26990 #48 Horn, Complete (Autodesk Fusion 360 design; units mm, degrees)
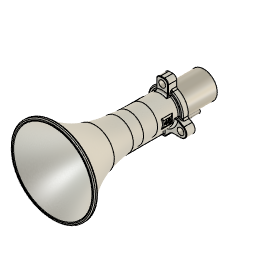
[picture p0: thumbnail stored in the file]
parameter "Bolt_Hole_Tolerance" = 1.5875 (= "( 1 / 16 ) * 1 in")
parameter "Dowel_Hole_Tolerance" = 0.0248 (= "( 1 / 1024 ) * 1 in")
canvas "Canvas1"
canvas "Canvas10"
sketch "Main Profile" plane through (0, 0, 0) normal (1, 0, 0) x axis (0, 1, 0)
  line L1 (0, -22.225) -> (0, 22.225)
  line L2 (-53.975, 22.225) -> (0, 22.225)
  line L3 (-53.975, 44.45) -> (-53.975, 22.225)
  line L4 (-248.4438, 0) -> (0, 0)
  line L5 (-68.2625, 44.45) -> (-53.975, 44.45)
  line L6 (-53.975, -22.225) -> (0, -22.225)
  line L7 (-53.975, 22.225) -> (-53.975, -22.225)
  line L8 (-53.975, -38.1) -> (-53.975, -22.225)
  line L9 (-68.2625, -38.1) -> (-53.975, -38.1)
  line L10 (-68.2625, 44.45) -> (-68.2625, -38.1)
  line L11 (-141.1977, 22.225) -> (0, 11.1125)
  line L12 (-63.5, 28.575) -> (-53.975, 28.575)
  line L13 (-63.5, 19.2949) -> (-63.5, 28.575)
  line L14 (-140.9486, 25.3902) -> (-63.5, 19.2949)
  line L15 (-248.4438, -69.0563) -> (-248.4437, 69.0562)
  line L16 (-68.2625, 19.6697) -> (-68.2625, 44.45)
  line L17 (9.1828, 34.925) -> (-68.2625, 34.925)
  line L18 (-34.1313, 22.225) -> (-34.1313, -22.225)
  line L19 (-68.2625, -18.1085) -> (-68.2625, -38.1)
  line L20 (-243.6812, 69.0562) -> (-248.4437, 69.0562)
  line L21 (-243.6813, 65.2268) -> (-243.6812, 69.0562)
  line L22 (-187.3946, -34.925) -> (-68.2625, -34.925)
  line L23 (-98.8407, 23.0188) -> (-68.2625, 23.0187)
  line L24 (-141.1977, 0) -> (-141.1977, 22.225)
  line L25 (-141.1977, -22.225) -> (0, -11.1125)
  line L26 (-243.6813, -65.2268) -> (-243.6812, -69.0563)
  line L27 (-243.6812, -69.0563) -> (-248.4437, -69.0563)
  line L28 (-98.8407, -23.0188) -> (-68.2625, -23.0188)
  line L29 (-140.9486, -25.3902) -> (-63.5, -19.2949)
  line L30 (-63.5, 23.0187) -> (-68.2625, 23.0187)
  arc A1 centre (-125.9018, 216.5783) radius 194.9543 clockwise from (-141.1977, 22.225) to (-248.4437, 64.9517)
  arc A2 centre (-125.9018, 216.5783) radius 191.7793 clockwise from (-140.9486, 25.3902) to (-248.4437, 69.0562)
  arc A3 centre (-125.9018, -216.5783) radius 194.9543 clockwise from (-248.4437, -64.9517) to (-141.1977, -22.225)
  arc A4 centre (-125.9018, -216.5783) radius 191.7793 clockwise from (-248.4437, -69.0563) to (-140.9486, -25.3902)
  arc A5 centre (-98.8407, 327.8188) radius 304.8 clockwise from (-98.8407, 23.0188) to (-122.755, 23.9583)
  arc A6 centre (-98.8407, -327.8188) radius 304.8 clockwise from (-122.755, -23.9583) to (-98.8407, -23.0188)
  point P4 (0, 0)
  point P1 (0, 0)
  point P7 (0, 0)
  point P13 (0, 11.1125)
  point P15 (-53.975, 28.575)
  point P21 (-248.4438, 0)
  point P8 (-248.4438, 0)
  point P22 (-68.2625, 19.6697)
  point P23 (-68.2625, 34.925)
  point P25 (-34.1313, -22.225)
  point P26 (-34.1313, 22.225)
  point P27 (-68.2625, -18.1085)
  point P30 (-68.2625, -34.925)
  point P32 (-68.2625, 23.0187)
  point P34 (-248.4437, 64.9517)
  point P38 (-141.1977, 0)
  point P36 (-248.4437, 69.0562)
  point P29 (-243.6813, 65.2268)
  point P19 (-248.4437, 69.0562)
  point P39 (0, -11.1125)
  point P14 (-141.1977, 22.225)
  point P40 (-141.1977, -22.225)
  point P17 (-63.5, 19.2949)
  point P51 (-63.5, -19.2949)
  point P18 (-140.9486, 25.3902)
  point P45 (-140.9486, -25.3902)
  point P48 (-248.4437, -69.0563)
  point P28 (-243.6812, 69.0562)
  point P46 (-243.6812, -69.0563)
  point P47 (-243.6813, -65.2268)
  point P49 (-68.2625, -23.0188)
  point P33 (-98.8407, 23.0188)
  point P50 (-98.8407, -23.0188)
  point P42 (-248.4437, -64.9517)
  point P44 (-248.4437, -69.0563)
  point P31 (-187.3946, -34.925)
  point P52 (-63.5, 23.0187)
  point P53 (-122.755, 23.9583)
  point P57 (-98.8407, -23.0188)
  point P56 (-122.755, -23.9583)
  point P2 (0, 22.225)
  point P5 (-53.975, 22.225)
  point P3 (0, -22.225)
  point P6 (-53.975, 44.45)
  point P9 (-68.2625, 44.45)
  point P16 (-63.5, 28.575)
  point P20 (-248.4438, -69.0563)
  point P12 (-68.2625, -38.1)
  vertical L1
  coincident L1 P4
  coincident P1 P4
  midpoint P1 L1
  perpendicular L1 L2
  perpendicular L2 L3
  coincident P1 P7
  perpendicular L1 L4
  perpendicular L3 L5
  perpendicular L1 L6
  vertical L7
  perpendicular L6 L8
  perpendicular L8 L9
  vertical L10
  coincident L1 P13
  coincident L3 P15
  perpendicular L3 L12
  perpendicular L12 L13
  parallel L11 L14
  vertical L15
  midpoint L15 P21
  coincident P8 P21
  coincident L14 P22
  coincident L10 P22
  coincident L10 P23
  perpendicular L16 L17
  coincident L6 P25
  coincident L2 P26
  perpendicular L2 L18
  coincident L10 P27
  perpendicular L9 L19
  perpendicular L15 L20
  vertical L21
  coincident L10 P30
  perpendicular L19 L22
  coincident L10 P32
  horizontal L23
  coincident L15 P34
  tangent L11 A1
  tangent L14 A2
  concentric A1 A2
  coincident L4 P38
  perpendicular L4 L24
  coincident L15 P36
  coincident P29 A2
  coincident P19 P36
  symmetric L4 P13 P39
  symmetric L4 P14 P40
  symmetric L4 P17 P51
  symmetric L4 P18 P45
  symmetric L4 P19 P48
  symmetric L4 P28 P46
  symmetric L4 P29 P47
  symmetric L4 P32 P49
  symmetric L4 P33 P50
  symmetric L4 P34 P42
  symmetric L4 A1 A3
  symmetric L4 P36 P44
  symmetric L4 A2 A4
  coincident P31 A4
  coincident L13 P52
  perpendicular L13 L30
  coincident L14 P53
  tangent L23 A5
  tangent L14 A5
  symmetric L4 P33 P57
  symmetric L4 P53 P56
  symmetric L4 A5 A6
  dimension "d1" distance P2 P5 = 53.975 (= "2 1/8")
  dimension "d2" distance P2 P3 = 44.45 (= "1 3/4")
  dimension "d3" distance P6 L4 = 44.45 (= "1 3/4")
  dimension "d4" distance P6 P9 = 14.2875 (= "( 9 / 16 ) * 1 in")
  dimension "d5" distance L4 L9 = 38.1
  dimension "d6" distance P4 P13 = 11.1125 (= "( 7 / 16 ) * 1 in")
  dimension "d7" distance L11 L14 = 3.175 (= "( 1 / 8 ) * 1 in")
  dimension "d9" distance P15 P16 = 9.525 (= "( 3 / 8 ) * 1 in")
  dimension "d10" distance L4 L12 = 28.575
  dimension "d11" distance L4 L17 = 34.925 (= "1 3/8")
  dimension "d12" distance P19 P20 = 138.1125 (= "5 7/16")
  dimension "d17" distance L1 L18 = 34.1313 (= "1 11/32")
  dimension "d68" distance P19 P28 = 4.7625 (= "( 3 / 16 ) * 1 in")
  dimension "d157" distance L15 L18 = 214.3125 (= "8 7/16")
  dimension "d175" distance P12 P30 = 3.175 (= "( 1 / 8 ) * 1 in")
  dimension "d197" angle L4 L11 = 4.5
  dimension "d198" distance L4 L23 = 23.0187 (= "( 29 / 32 ) * 1 in")
  dimension "d290" distance P14 P38 = 22.225 (= "( 7 / 8 ) * 1 in")
  dimension "d293" radius A5 = 304.8
revolve "Revolve1" sketch "Main Profile" AlongAngle 360
revolve "Revolve3" sketch "Main Profile" AlongAngle 360
fillet "Fillet16" radius 158.75
sketch "Flange Profile" plane through (0, -53.975, 0) normal (0, 1, 0) x axis (-1, 0, 0)
  line L1 (0, 34.925) -> (0, 0)
  line L2 (0, 44.45) -> (0, 34.925)
  line L3 (3.175, 44.45) -> (-3.175, 44.45)
  line L4 (9.525, 31.1085) -> (9.525, 38.1)
  line L5 (-30.2459, -17.4625) -> (0, 0)
  line L6 (30.2459, -17.4625) -> (0, 0)
  line L7 (30.2459, -26.9875) -> (15.0812, -26.9875)
  line L8 (29.9633, -6.3008) -> (35.0084, -9.2136)
  line L9 (0, -31.75) -> (0, 0)
  line L10 (0, -38.1) -> (0, -31.75)
  line L11 (3.9688, -38.1) -> (-3.9688, -38.1)
  line L12 (15.0812, -26.9875) -> (3.9688, -38.1)
  line L13 (-15.0812, -26.9875) -> (-3.9688, -38.1)
  line L14 (-30.2459, -26.9875) -> (-15.0812, -26.9875)
  line L15 (-29.9633, -6.3008) -> (-35.0084, -9.2136)
  line L16 (-9.525, 31.1085) -> (-9.525, 38.1)
  line L17 (9.525, 20.0805) -> (9.525, 31.1085)
  line L18 (-9.525, 20.0805) -> (-9.525, 31.1085)
  line L19 (22.1527, -1.7913) -> (29.9633, -6.3008)
  line L20 (-22.1527, -1.7913) -> (-29.9633, -6.3008)
  circle C1 centre (0, 0) radius 22.225
  circle C2 centre (0, 34.925) radius 5.5563
  arc A1 centre (3.175, 38.1) radius 6.35 clockwise from (3.175, 44.45) to (9.525, 38.1)
  arc A2 centre (15.875, 31.1085) radius 6.35 clockwise from (12.9886, 25.4524) to (9.525, 31.1085)
  arc A3 centre (0, 0) radius 28.575 clockwise from (12.9886, 25.4524) to (28.3957, -3.196)
  circle C3 centre (-30.2459, -17.4625) radius 5.5563
  circle C4 centre (30.2459, -17.4625) radius 5.5563
  arc A4 centre (30.2459, -17.4625) radius 9.525 clockwise from (35.0084, -9.2136) to (30.2459, -26.9875)
  arc A5 centre (31.5508, -3.5512) radius 3.175 clockwise from (29.9633, -6.3008) to (28.3957, -3.196)
  circle C5 centre (0, -31.75) radius 3.9688
  arc A6 centre (-30.2459, -17.4625) radius 9.525 clockwise from (-30.2459, -26.9875) to (-35.0084, -9.2136)
  arc A7 centre (-31.5508, -3.5512) radius 3.175 clockwise from (-28.3957, -3.196) to (-29.9633, -6.3008)
  arc A8 centre (0, 0) radius 28.575 clockwise from (-28.3957, -3.196) to (-12.9886, 25.4524)
  arc A9 centre (-15.875, 31.1085) radius 6.35 clockwise from (-9.525, 31.1085) to (-12.9886, 25.4524)
  arc A10 centre (-3.175, 38.1) radius 6.35 clockwise from (-9.525, 38.1) to (-3.175, 44.45)
  circle C6 centre (0, 0) radius 28.575
  point P1 (0, 0)
  point P3 (0, 0)
  point P4 (0, 34.925)
  point P5 (0, 34.925)
  point P6 (0, 34.925)
  point P10 (0, 44.45)
  point P7 (0, 44.45)
  point P30 (0, 0)
  point P31 (0, -31.75)
  point P32 (0, -31.75)
  point P33 (0, -31.75)
  point P37 (0, -38.1)
  point P34 (0, -38.1)
  point P9 (3.175, 44.45)
  point P52 (-3.175, 44.45)
  point P11 (9.525, 38.1)
  point P50 (-9.525, 38.1)
  point P13 (9.525, 31.1085)
  point P49 (-9.525, 31.1085)
  point P14 (12.9886, 25.4524)
  point P47 (-12.9886, 25.4524)
  point P16 (28.3957, -3.196)
  point P45 (-28.3957, -3.196)
  point P24 (15.0812, -26.9875)
  point P39 (-15.0812, -26.9875)
  point P25 (30.2459, -26.9875)
  point P40 (-30.2459, -26.9875)
  point P26 (35.0084, -9.2136)
  point P42 (-35.0084, -9.2136)
  point P28 (29.9633, -6.3008)
  point P43 (-29.9633, -6.3008)
  point P36 (3.9688, -38.1)
  point P38 (-3.9688, -38.1)
  point P53 (9.525, 20.0805)
  point P54 (-9.525, 20.0805)
  point P55 (22.1527, -1.7913)
  point P56 (-22.1527, -1.7913)
  point P35 (-3.9688, -38.1)
  point P19 (0, 0)
  coincident P1 P3
  vertical L1
  coincident P4 P5
  coincident P5 P6
  parallel L1 L2
  horizontal L3
  coincident L3 P10
  midpoint L3 P10
  coincident P7 P10
  tangent L3 A1
  vertical L4
  tangent A1 L4
  tangent L4 A2
  tangent A2 A3
  concentric C1 A3
  horizontal L7
  tangent L7 A4
  concentric C4 A4
  tangent A4 L8
  tangent L8 A5
  tangent A3 A5
  coincident P1 P30
  vertical L9
  coincident P31 P32
  coincident P32 P33
  parallel L9 L10
  horizontal L11
  midpoint L11 P37
  coincident P34 P37
  symmetric L1 P9 P52
  symmetric L1 P11 P50
  symmetric L1 A1 A10
  symmetric L1 P13 P49
  symmetric L1 P14 P47
  symmetric L1 A2 A9
  symmetric L1 P16 P45
  symmetric L1 A3 A8
  symmetric L1 P24 P39
  symmetric L1 P25 P40
  symmetric L1 P26 P42
  symmetric L1 A4 A6
  symmetric L1 P28 P43
  symmetric L1 A5 A7
  symmetric L1 P36 P38
  coincident C1 P53
  tangent A2 L17
  tangent A9 L18
  coincident C1 P54
  coincident C1 P55
  tangent A5 L19
  coincident C1 P56
  tangent A7 L20
  dimension "d95" distance P3 P4 = 34.925 (= "1 3/8")
  dimension "d96" diameter C2 = 11.1125 (= "( 3 / 8 ) * 1 in + Bolt_Hole_Tolerance")
  dimension "d97" radius A1 = 6.35 (= "( 1 / 4 ) * 1 in")
  dimension "d98" distance P1 L3 = 44.45 (= "1 3/4")
  dimension "d99" distance P5 L4 = 9.525 (= "( 3 / 8 ) * 1 in")
  dimension "d100" radius A2 = 6.35 (= "( 1 / 4 ) * 1 in")
  dimension "d101" radius A3 = 28.575 (= "1 1/8")
  dimension "d104" radius A4 = 9.525 (= "( 3 / 8 ) * 1 in")
  dimension "d105" angle L7 L8 = 30
  dimension "d106" radius A5 = 3.175 (= "( 1 / 8 ) * 1 in")
  dimension "d107" distance P30 P31 = 31.75 (= "1 1/4")
  dimension "d108" diameter C5 = 7.9375 (= "( 5 / 16 ) * 1 in")
  dimension "d109" distance P35 P36 = 7.9375 (= "( 5 / 16 ) * 1 in")
  dimension "d110" angle L7 L12 = 135
  dimension "d111" distance P19 L11 = 38.1 (= "1 1/2")
  dimension "d103" C-Pattern1-Angle = 360
extrude "Extrude2" add sketch "Flange Profile" profile of C1 C2 L3 A1 L4 C3 C4 L7 A4 L8 C5 L11 L12 L13 L14 A6 L15 L16 A10 L17 L18 L19 L20 against normal blind 14.2875 (magnitude of "( -9 / 16 ) * 1 in")
extrude "Extrude6" add sketch "Main Profile" profile of L19 L22 along normal blind 3.175 (= "( 1 / 8 ) * 1 in")
mirror "Mirror5" mirrorStitchTolerance 0.1016
delete_face "DeleteFace14"
delete_face "DeleteFace15"
extrude "Extrude4" cut sketch "Flange Profile" profile of C2 C3 C4 against normal blind 14.3002
extrude "Extrude5" cut sketch "Flange Profile" profile of C5 against normal blind 9.525 (magnitude of "( -3 / 8 ) * 1 in")
fillet "Fillet27" radius 3.175 (= "( 1 / 8 ) * 1 in")
fillet "Fillet28" radius 1.5875 (= "( 1 / 16 ) * 1 in")
fillet "Fillet29" radius 34.925 (= "1 3/8")
fillet "Fillet30" radius 1.5875 (= "( 1 / 16 ) * 1 in")
fillet "Fillet31" radius 0.7937 (= "( 1 / 32 ) * 1 in")
sketch "Main Profile" plane through (0, -63.5, 0) normal (0, 1, 0) x axis (-1, 0, 0)
  circle C1 centre (0, -31.75) radius 3.9687
  circle C2 centre (0, -31.75) radius 3.175
  concentric C1 C2
  dimension "d137" diameter C2 = 6.35 (= "( 1 / 4 ) * 1 in")
extrude "Extrude1" new body sketch "Main Profile" along normal blind 53.975 (= "2 1/8") bodies "27281 Orifice Pin #5"
offset_faces "OffsetFaces1"
work_plane "WorkPlane1" RotateAngle -180
sketch "Orifice & Number Profile" plane through (0, -43.2509, -35.7188) normal (0, 0, -1) x axis (1, 0, 0)
  line L1 (3.9688, -33.7259) -> (-3.9687, -33.7259)
  line L2 (3.9688, 20.2491) -> (-3.9687, 20.2491)
  line L3 (0, 20.2491) -> (0, -33.7259)
  line L4 (-22.225, -43.2509) -> (22.225, -43.2509)
  line L5 (1.5875, -9.1196) -> (1.5875, -33.7259)
  line L6 (0, -9.1196) -> (1.5875, -9.1196)
  circle C1 centre (0, -9.1196) radius 0.9922
  point P6 (0, -33.7259)
  point P7 (0, 20.2491)
  point P8 (0, -9.1196)
  point P11 (1.5875, -33.7259)
  point P13 (0, -9.1196)
  point P12 (1.5875, -9.1196)
  midpoint L1 P6
  midpoint L2 P7
  coincident L3 P8
  coincident L1 P11
  perpendicular L1 L5
  coincident L3 P13
  perpendicular L3 L6
  coincident P8 P13
  dimension "d143" diameter C1 = 1.9844 (= "( 5 / 64 ) * 1 in")
  dimension "d144" distance P8 L4 = 34.1313
  dimension "d145" distance P12 P13 = 1.5875 (= "( 1 / 16 ) * 1 in")
  dimension "d146" Text1-Height = 3.175 (= "( 1 / 8 ) * 1 in")
emboss "Emboss1" sketch "Orifice & Number Profile" Depth -0.1984 (= "( -1 / 128 ) * 1 in") Horizontal Distance 0 Vertical Distance 0 Rotation Angle 0
extrude "Extrude2" cut sketch "Orifice & Number Profile" profile of C1 against normal blind 3.175 (magnitude of "( -1 / 8 ) * 1 in")
fillet "Fillet32" radius 1.5875 (= "( 1 / 16 ) * 1 in")
sketch "Branding Profile 1" plane through (0, 0, 0) normal (0, 0, 1) x axis (1, 0, 0)
  line L1 (22.9839, -65.0875) -> (22.9839, -71.4375)
  line L2 (10.3956, -65.0875) -> (23.0187, -65.0875)
  line L3 (10.3956, -71.4375) -> (10.3956, -65.0875)
  line L4 (-10.3956, -65.0875) -> (-10.3956, -71.4375)
  line L5 (-23.0187, -65.0875) -> (-10.3956, -65.0875)
  line L6 (-22.9839, -71.4375) -> (-22.9839, -65.0875)
  line L7 (-23.0188, -71.4375) -> (-23.0187, -98.8407)
  line L8 (-23.2172, -76.198) -> (-21.4313, -76.2163)
  line L9 (-23.6094, -114.2959) -> (-23.2172, -76.198)
  line L10 (-21.8235, -114.3143) -> (-23.6094, -114.2959)
  line L11 (-21.4313, -76.2163) -> (-21.8235, -114.3143)
  line L12 (-25.7527, -68.2625) -> (-34.6116, -68.2625)
  line L13 (-32.3616, -179.2259) -> (32.3614, -179.2259)
  line L14 (21.4313, -76.2) -> (23.4156, -76.2)
  line L15 (21.4312, -88.9) -> (21.4313, -76.2)
  line L16 (23.4156, -88.9) -> (21.4312, -88.9)
  line L17 (23.4156, -76.2) -> (23.4156, -88.9)
  line L18 (0, 50.8) -> (0, 0)
  line L19 (23.0188, -71.4375) -> (23.0187, -98.8407)
  line L20 (34.6116, -68.2625) -> (25.7527, -68.2625)
  line L21 (-23.0187, -98.8407) -> (23.0187, -98.8407)
  line L22 (-25.3902, -140.9486) -> (25.3902, -140.9486)
  line L23 (4.4552, -71.4375) -> (4.4552, -98.8407)
  line L24 (4.4552, -71.4375) -> (22.9839, -71.4375)
  line L25 (-10.3956, -71.4375) -> (10.3956, -71.4375)
  line L26 (-22.9839, -71.4375) -> (-4.4552, -71.4375)
  line L27 (-4.4552, -98.8407) -> (-4.4552, -71.4375)
  curve K1 (4.5413, -179.2259) -> (4.5466, -178.4873)
  curve K2 (-4.5466, -178.4873) -> (-4.5413, -179.2259)
  line L28 (-23.9583, -122.755) -> (23.9583, -122.755)
  arc A1 centre (-327.8188, -98.8407) radius 304.8 clockwise from (-23.0187, -98.8407) to (-23.9583, -122.755)
  point P17 (-23.4109, -114.298)
  point P18 (-23.0187, -76.2)
  point P1 (0, 0)
  point P27 (0, 0)
  point P29 (23.0187, -98.8407)
  point P38 (-23.0187, -98.8407)
  point P12 (-23.0188, -71.4375)
  point P30 (23.0188, -71.4375)
  point P31 (23.0187, -76.2)
  point P49 (-23.0187, -98.8407)
  point P34 (-23.0187, -98.8407)
  point P35 (-23.9583, -122.755)
  point P51 (-23.9583, -122.755)
  point P15 (-23.6094, -114.2959)
  point P13 (-21.4313, -76.2163)
  point P14 (-23.2172, -76.198)
  point P23 (23.4156, -76.2)
  point P26 (23.4156, -88.9)
  vertical L7
  perpendicular L8 L9
  perpendicular L9 L10
  perpendicular L10 L11
  coincident L10 P17
  coincident L8 P18
  coincident L7 P18
  perpendicular L14 L15
  perpendicular L15 L16
  perpendicular L16 L17
  coincident P1 P27
  vertical L18
  symmetric L18 P29 P38
  symmetric P12 L18 P30
  coincident L19 P31
  coincident L14 P31
  vertical L17
  tangent L7 A1
  coincident P17 A1
  coincident P38 P49
  coincident P12 L26
  coincident P34 P49
  coincident P35 L28
  coincident P35 P51
  dimension "d216" distance P18 L12 = 7.9375 (= "( 5 / 16 ) * 1 in")
  dimension "d217" distance P15 P17 = 0.1984 (= "( 1 / 128 ) * 1 in")
  dimension "d218" = 0.1984 (= "d217")
  dimension "d219" distance P13 P18 = 1.5875 (= "( 1 / 16 ) * 1 in")
  dimension "d242" distance P14 P15 = 38.1 (= "1 1/2")
  dimension "d260" distance P23 P31 = 0.3969 (= "( 1 / 64 ) * 1 in")
  dimension "d263" distance P31 L20 = 7.9375 (= "( 5 / 16 ) * 1 in")
  dimension "d264" distance P23 P26 = 12.7 (= "( 1 / 2 ) * 1 in")
  dimension "d292" distance L15 L19 = 1.5875 (= "( 1 / 16 ) * 1 in")
extrude "Extrude10" add sketch "Branding Profile 1" profile of L7 L8 L9 L10 L11 distance 19.05 (= "( 3 / 4 ) * 1 in")
delete_face "DeleteFace16"
sketch "Branding Profile 2" plane through (-22.4304, 0.2309, 0) normal (-0.9999, 0.0103, 0) x axis (-0.0103, -0.9999, 0)
  line L1 (114.5329, 9.525) -> (114.5329, -9.525)
  line L2 (76.4329, 9.525) -> (114.5329, 9.525)
  line L3 (76.4329, -9.525) -> (76.4329, 9.525)
  line L4 (114.5329, -9.525) -> (76.4329, -9.525)
  line L5 (94.6103, -1.131) -> (92.2224, 2.1371)
  line L6 (108.9955, -0.9686) -> (109.523, -0.9686)
  line L7 (102.3363, -4.8781) -> (102.3363, -5.6373)
  line L8 (96.0576, 3.3576) -> (96.0576, 4.8791)
  line L9 (89.0662, -0.4801) -> (89.0662, 0.0594)
  line L10 (90.6251, 4.8553) -> (90.6251, 5.2322)
  line L11 (92.1406, 2.3877) -> (92.1406, 4.8031)
  line L12 (95.663, 5.2738) -> (92.6113, 5.2738)
  line L13 (94.9004, -4.2813) -> (94.9004, -2.0198)
  line L14 (90.8546, -5.0959) -> (90.8546, -5.528)
  line L15 (87.7546, -4.4596) -> (87.7546, -1.4472)
  line L16 (96.4069, -5.0326) -> (96.4069, -1.5281)
  line L17 (82.916, -6.7702) -> (83.9845, -6.2258)
  line L18 (88.2381, -0.9636) -> (88.5827, -0.9636)
  line L19 (82.1503, -6.301) -> (82.1503, 7.809)
  line L20 (80.5158, -8.3956) -> (80.5158, 8.2084)
  line L21 (86.2481, -6.3626) -> (86.2481, 6.0597)
  line L22 (84.4791, -7.7782) -> (81.765, -9.1611)
  line L23 (90.4738, -6.0315) -> (87.0808, -6.9922)
  line L24 (93.1671, -4.2813) -> (93.1671, -2.0448)
  line L25 (84.8722, -6.7697) -> (84.8722, -7.1367)
  line L26 (108.6189, 0.9145) -> (108.6189, -1.3453)
  line L27 (109.8997, -0.592) -> (109.8997, 0.1613)
  line L28 (110.5811, 9.0165) -> (107.4447, 7.6922)
  line L29 (87.7546, 1.0264) -> (87.7546, 3.9726)
  line L30 (88.6243, 4.6563) -> (89.9593, 4.3319)
  line L31 (87.7546, 1.0264) -> (87.7546, -1.4472)
  line L32 (81.9484, 8.1969) -> (81.3281, 8.6312)
  line L33 (106.9844, -6.6138) -> (106.9844, 6.9982)
  line L34 (101.9127, -6.011) -> (98.5373, -5.5871)
  line L35 (105.2694, 6.3232) -> (105.2694, -6.3604)
  line L36 (96.1168, -0.6393) -> (93.5293, 2.9021)
  line L37 (99.7142, -4.2166) -> (102.0066, -4.5044)
  line L38 (103.7628, -6.1011) -> (103.7628, 6.0639)
  line L39 (92.7998, -5.4092) -> (96.0303, -5.4092)
  line L40 (94.5163, -4.6653) -> (93.5512, -4.6653)
  line L41 (108.6189, -5.948) -> (108.6189, -1.3453)
  line L42 (99.3844, -3.8429) -> (99.3844, 5.1103)
  line L43 (110.9782, -7.2726) -> (108.8384, -6.2903)
  line L44 (88.5917, -5.0926) -> (90.2349, -4.6273)
  line L45 (93.4458, 3.158) -> (93.4458, 3.5592)
  line L46 (107.4234, -7.2984) -> (110.6639, -8.7861)
  line L47 (104.7701, -6.7165) -> (104.0168, -6.4572)
  line L48 (90.2127, 5.7567) -> (86.8896, 6.5641)
  line L49 (97.8779, -4.8397) -> (97.8779, 5.1103)
  line L50 (111.1977, -8.4438) -> (111.1977, -7.6149)
  line L51 (92.4232, -2.0448) -> (92.4232, -5.0326)
  line L52 (92.7905, -1.6682) -> (92.7998, -1.6682)
  line L53 (94.775, 3.8359) -> (94.8682, 3.2617)
  line L54 (93.4458, 3.5592) -> (93.4458, 3.7743)
  line L55 (109.523, 0.5379) -> (108.9955, 0.5379)
  line L56 (111.1043, 7.8519) -> (111.1043, 8.6696)
  line L57 (108.849, 6.6498) -> (110.8742, 7.5049)
  line L58 (99.0078, 5.487) -> (98.2545, 5.487)
  line L59 (93.8298, 4.1584) -> (94.3959, 4.1584)
  line L60 (104.0168, 6.42) -> (104.7701, 6.6793)
  line L61 (108.6189, 0.9145) -> (108.6189, 6.3029)
  line L62 (88.5827, 0.5429) -> (88.2381, 0.5429)
  arc A1 centre (94.3959, 3.7743) radius 0.3841 clockwise from (94.3959, 4.1584) to (94.775, 3.8359)
  arc A2 centre (99.7611, -3.8429) radius 0.3766 clockwise from (99.7142, -4.2166) to (99.3844, -3.8429)
  arc A3 centre (110.8211, -7.6149) radius 0.3766 clockwise from (110.9782, -7.2726) to (111.1977, -7.6149)
  arc A4 centre (81.032, 8.2084) radius 0.5162 clockwise from (80.5158, 8.2084) to (81.3281, 8.6312)
  arc A5 centre (109.523, -0.592) radius 0.3766 clockwise from (109.8997, -0.592) to (109.523, -0.9686)
  arc A6 centre (88.4582, 3.9726) radius 0.7035 clockwise from (87.7546, 3.9726) to (88.6243, 4.6563)
  arc A7 centre (90.0853, 5.2322) radius 0.5398 clockwise from (90.2127, 5.7567) to (90.6251, 5.2322)
  arc A8 centre (95.663, 4.8791) radius 0.3947 clockwise from (95.663, 5.2738) to (96.0576, 4.8791)
  arc A9 centre (92.5654, 2.3877) radius 0.4248 clockwise from (92.2224, 2.1371) to (92.1406, 2.3877)
  arc A10 centre (92.7905, -2.0448) radius 0.3766 clockwise from (92.7905, -1.6682) to (93.1671, -2.0448)
  arc A11 centre (88.2381, -1.4472) radius 0.4835 clockwise from (87.7546, -1.4472) to (88.2381, -0.9636)
  arc A12 centre (92.7998, -5.0326) radius 0.3766 clockwise from (92.7998, -5.4092) to (92.4232, -5.0326)
  arc A13 centre (88.5827, -0.4801) radius 0.4835 clockwise from (89.0662, -0.4801) to (88.5827, -0.9636)
  arc A14 centre (81.375, -8.3956) radius 0.8592 clockwise from (81.765, -9.1611) to (80.5158, -8.3956)
  arc A15 centre (90.3676, -5.0959) radius 0.487 clockwise from (90.2349, -4.6273) to (90.8546, -5.0959)
  arc A16 centre (84.2617, -6.7697) radius 0.6105 clockwise from (83.9845, -6.2258) to (84.8722, -6.7697)
  arc A17 centre (93.3938, -2.0198) radius 1.5065 clockwise from (94.6103, -1.131) to (94.9004, -2.0198)
  arc A18 centre (82.6769, -6.301) radius 0.5266 clockwise from (82.916, -6.7702) to (82.1503, -6.301)
  arc A19 centre (94.9004, -1.5281) radius 1.5065 clockwise from (96.1168, -0.6393) to (96.4069, -1.5281)
  arc A20 centre (108.9955, 0.9145) radius 0.3766 clockwise from (108.9955, 0.5379) to (108.6189, 0.9145)
  arc A21 centre (108.9955, 6.3029) radius 0.3766 clockwise from (108.6189, 6.3029) to (108.849, 6.6498)
  arc A22 centre (98.2545, 5.1103) radius 0.3766 clockwise from (97.8779, 5.1103) to (98.2545, 5.487)
  arc A23 centre (104.1395, 6.0639) radius 0.3766 clockwise from (103.7628, 6.0639) to (104.0168, 6.42)
  arc A24 centre (88.2381, 1.0264) radius 0.4835 clockwise from (88.2381, 0.5429) to (87.7546, 1.0264)
  arc A25 centre (90.0865, 4.8553) radius 0.5386 clockwise from (90.6251, 4.8553) to (89.9593, 4.3319)
  arc A26 centre (93.8796, 3.158) radius 0.4338 clockwise from (93.5293, 2.9021) to (93.4458, 3.158)
  arc A27 centre (99.0078, 5.1103) radius 0.3766 clockwise from (99.0078, 5.487) to (99.3844, 5.1103)
  arc A28 centre (107.7377, -6.6138) radius 0.7533 clockwise from (107.4234, -7.2984) to (106.9844, -6.6138)
  arc A29 centre (101.9597, -5.6373) radius 0.3766 clockwise from (102.3363, -5.6373) to (101.9127, -6.011)
  arc A30 centre (108.9955, -1.3453) radius 0.3766 clockwise from (108.6189, -1.3453) to (108.9955, -0.9686)
  arc A31 centre (110.8211, -8.4438) radius 0.3766 clockwise from (111.1977, -8.4438) to (110.6639, -8.7861)
  arc A32 centre (88.5827, 0.0594) radius 0.4835 clockwise from (88.5827, 0.5429) to (89.0662, 0.0594)
  arc A33 centre (92.7998, -2.0448) radius 0.3766 clockwise from (92.4232, -2.0448) to (92.7998, -1.6682)
  arc A34 centre (96.0303, -5.0326) radius 0.3766 clockwise from (96.4069, -5.0326) to (96.0303, -5.4092)
  arc A35 centre (90.3312, -5.528) radius 0.5233 clockwise from (90.8546, -5.528) to (90.4738, -6.0315)
  arc A36 centre (104.8927, -6.3604) radius 0.3766 clockwise from (105.2694, -6.3604) to (104.7701, -6.7165)
  arc A37 centre (101.9597, -4.8781) radius 0.3766 clockwise from (102.0066, -4.5044) to (102.3363, -4.8781)
  arc A38 centre (88.4125, -4.4596) radius 0.6578 clockwise from (88.5917, -5.0926) to (87.7546, -4.4596)
  arc A39 centre (94.5163, -4.2813) radius 0.3841 clockwise from (94.9004, -4.2813) to (94.5163, -4.6653)
  arc A40 centre (93.5512, -4.2813) radius 0.3841 clockwise from (93.5512, -4.6653) to (93.1671, -4.2813)
  arc A41 centre (98.6312, -4.8397) radius 0.7533 clockwise from (98.5373, -5.5871) to (97.8779, -4.8397)
  arc A42 centre (81.6768, 7.809) radius 0.4736 clockwise from (81.9484, 8.1969) to (82.1503, 7.809)
  arc A43 centre (86.9025, -6.3626) radius 0.6544 clockwise from (87.0808, -6.9922) to (86.2481, -6.3626)
  arc A44 centre (92.6113, 4.8031) radius 0.4706 clockwise from (92.1406, 4.8031) to (92.6113, 5.2738)
  arc A45 centre (108.9955, -5.948) radius 0.3766 clockwise from (108.8384, -6.2903) to (108.6189, -5.948)
  arc A46 centre (84.1523, -7.1367) radius 0.7199 clockwise from (84.8722, -7.1367) to (84.4791, -7.7782)
  arc A47 centre (104.1395, -6.1011) radius 0.3766 clockwise from (104.0168, -6.4572) to (103.7628, -6.1011)
  arc A48 centre (93.8298, 3.7743) radius 0.3841 clockwise from (93.4458, 3.7743) to (93.8298, 4.1584)
  arc A49 centre (95.4591, 3.3576) radius 0.5986 clockwise from (96.0576, 3.3576) to (94.8682, 3.2617)
  arc A50 centre (104.8927, 6.3232) radius 0.3766 clockwise from (104.7701, 6.6793) to (105.2694, 6.3232)
  arc A51 centre (107.7377, 6.9982) radius 0.7533 clockwise from (106.9844, 6.9982) to (107.4447, 7.6922)
  arc A52 centre (110.7276, 7.8519) radius 0.3766 clockwise from (111.1043, 7.8519) to (110.8742, 7.5049)
  arc A53 centre (110.7276, 8.6696) radius 0.3766 clockwise from (110.5811, 9.0165) to (111.1043, 8.6696)
  arc A54 centre (109.523, 0.1613) radius 0.3766 clockwise from (109.523, 0.5379) to (109.8997, 0.1613)
  arc A55 centre (86.7671, 6.0597) radius 0.519 clockwise from (86.2481, 6.0597) to (86.8896, 6.5641)
  point P152 (82.1503, -6.301)
  point P158 (82.1503, -6.301)
  point P82 (99.3844, -3.8429)
  point P90 (99.3844, -3.8429)
  point P95 (109.8997, -0.2154)
  point P106 (106.9844, -6.6138)
  point P170 (106.9844, -6.6138)
  tangent A4 L20
  tangent A4 L32
  tangent L32 A42
  tangent L19 A42
  vertical L19
  tangent A14 L20
  tangent A14 L22
  tangent L22 A46
  vertical L25
  tangent L25 A46
  tangent A16 L25
  tangent L17 A16
  parallel L17 L22
  tangent L17 A18
  coincident P152 P158
  tangent L19 A18
  vertical L21
  tangent L21 A55
  tangent L48 A55
  tangent A7 L48
  tangent A7 L10
  vertical L10
  tangent L10 A25
  tangent A25 L30
  parallel L30 L48
  tangent A6 L30
  vertical L29
  tangent A6 L29
  tangent A24 L29
  tangent A24 L62
  horizontal L62
  tangent A32 L62
  tangent L9 A32
  vertical L9
  tangent L9 A13
  horizontal L18
  tangent A13 L18
  tangent A11 L18
  vertical L15
  tangent A11 L15
  vertical L31
  tangent L21 A43
  tangent L23 A43
  tangent L23 A35
  vertical L14
  tangent L14 A35
  tangent L14 A15
  tangent A15 L44
  tangent A38 L44
  tangent L15 A38
  parallel L23 L44
  horizontal L12
  tangent A8 L12
  vertical L8
  tangent A8 L8
  tangent L8 A49
  tangent A49 L53
  tangent A1 L53
  tangent A1 L59
  horizontal L59
  tangent A48 L59
  vertical L54
  tangent A48 L54
  tangent L12 A44
  vertical L11
  tangent L11 A44
  tangent L11 A9
  tangent L5 A9
  parallel L45 L54
  tangent A26 L45
  tangent A26 L36
  parallel L5 L36
  tangent A19 L36
  vertical L16
  tangent L16 A19
  tangent L5 A17
  tangent L13 A17
  vertical L13
  tangent L16 A34
  horizontal L39
  tangent A34 L39
  tangent A12 L39
  vertical L51
  tangent A12 L51
  tangent A33 L51
  horizontal L52
  tangent A33 L52
  tangent A10 L52
  vertical L24
  tangent A10 L24
  tangent L24 A40
  tangent L13 A39
  tangent L40 A40
  tangent A39 L40
  vertical L49
  tangent A22 L49
  horizontal L58
  tangent A22 L58
  tangent A27 L58
  vertical L42
  tangent A27 L42
  tangent A41 L49
  tangent L34 A41
  tangent A29 L34
  vertical L7
  tangent L7 A29
  tangent L7 A37
  tangent L37 A37
  parallel L34 L37
  tangent A2 L37
  coincident P82 P90
  tangent A2 L42
  vertical L38
  tangent L38 A47
  tangent L47 A47
  tangent A36 L47
  vertical L35
  tangent L35 A36
  tangent L35 A50
  tangent A50 L60
  tangent A23 L60
  tangent A23 L38
  tangent L33 A51
  tangent L28 A51
  tangent L28 A53
  tangent L56 A53
  vertical L56
  tangent L56 A52
  tangent L57 A52
  parallel L28 L57
  tangent A21 L57
  vertical L61
  tangent A21 L61
  tangent A20 L61
  horizontal L55
  tangent A20 L55
  tangent L55 A54
  vertical L27
  tangent L27 A54
  tangent A5 L27
  horizontal L6
  tangent L6 A5
  tangent L6 A30
  vertical L41
  tangent A30 L41
  vertical L26
  midpoint P95 L27
  tangent L41 A45
  tangent L43 A45
  tangent A3 L43
  vertical L50
  tangent A3 L50
  tangent A31 L50
  tangent A31 L46
  parallel L43 L46
  tangent A28 L46
  coincident P106 P170
  tangent A28 L33
  dimension "d357" angle L20 L32 = 55
  dimension "d359" angle L20 L22 = 63
  dimension "d367" angle L8 L53 = 9.219
  dimension "d371" radius A9 = 0.4248
  dimension "d384" distance L12 L59 = 1.1154
  dimension "d395" angle L38 L47 = 109
  dimension "d400" angle L38 L60 = 109
  dimension "d339" angle L43 L50 = 114.659
extrude "Extrude11" add sketch "Branding Profile 2" profile of A1 A2 L5 L6 A3 L7 A4 A5 A6 A7 A8 L8 L9 L10 L11 L12 A9 L13 A10 A11 A12 A13 L14 A14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 along a picked direction blind 0.3969 (= "( 1 / 64 ) * 1 in") taper -30
fillet "Fillet33" radius 6.35 (= "( 1 / 4 ) * 1 in")
fillet "Fillet34" radius 3.175 (= "( 1 / 8 ) * 1 in")
fillet "Fillet35" radius 0.7937 (= "( 1 / 32 ) * 1 in")
extrude "Extrude14" add sketch "Branding Profile 1" profile of L14 L15 L16 L17 L19 distance 9.525 (= "( 3 / 8 ) * 1 in")
sketch "Branding Profile 4" plane through (23.4156, 0, 0) normal (1, 0, 0) x axis (0, 1, 0)
  line L1 (-76.2, 4.7625) -> (-76.2, -4.7625)
  line L2 (-88.9, 4.7625) -> (-76.2, 4.7625)
  line L3 (-88.9, -4.7625) -> (-88.9, 4.7625)
  line L4 (-76.2, -4.7625) -> (-88.9, -4.7625)
  line L5 (-76.2, -3.175) -> (-88.9, -3.175)
  line L6 (-88.9, 0) -> (-76.2, 0)
  point P6 (-88.9, -3.175)
  point P7 (-76.2, -3.175)
  point P8 (-76.2, 0)
  point P9 (-88.9, 0)
  coincident L3 P6
  coincident L1 P7
  perpendicular L1 L5
  midpoint L1 P8
  midpoint L3 P9
  dimension "d269" distance L5 L6 = 3.175 (= "( 1 / 8 ) * 1 in")
  dimension "d268" Text1-Height = 9.525 (= "( 3 / 8 ) * 1 in")
extrude "Extrude15" add sketch "Branding Profile 4" along normal blind 0.3969 (= "( 1 / 64 ) * 1 in") taper -25
fillet "Fillet45" radius 6.35 (= "( 1 / 4 ) * 1 in")
fillet "Fillet46" radius 3.175 (= "( 1 / 8 ) * 1 in")
fillet "Fillet47" radius 0.7937 (= "( 1 / 32 ) * 1 in")
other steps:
create_component "CreateComponent1"
create_component "CreateComponent2"
named bodies: "27281 Orifice Pin #5", "26990 #48 Horn"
